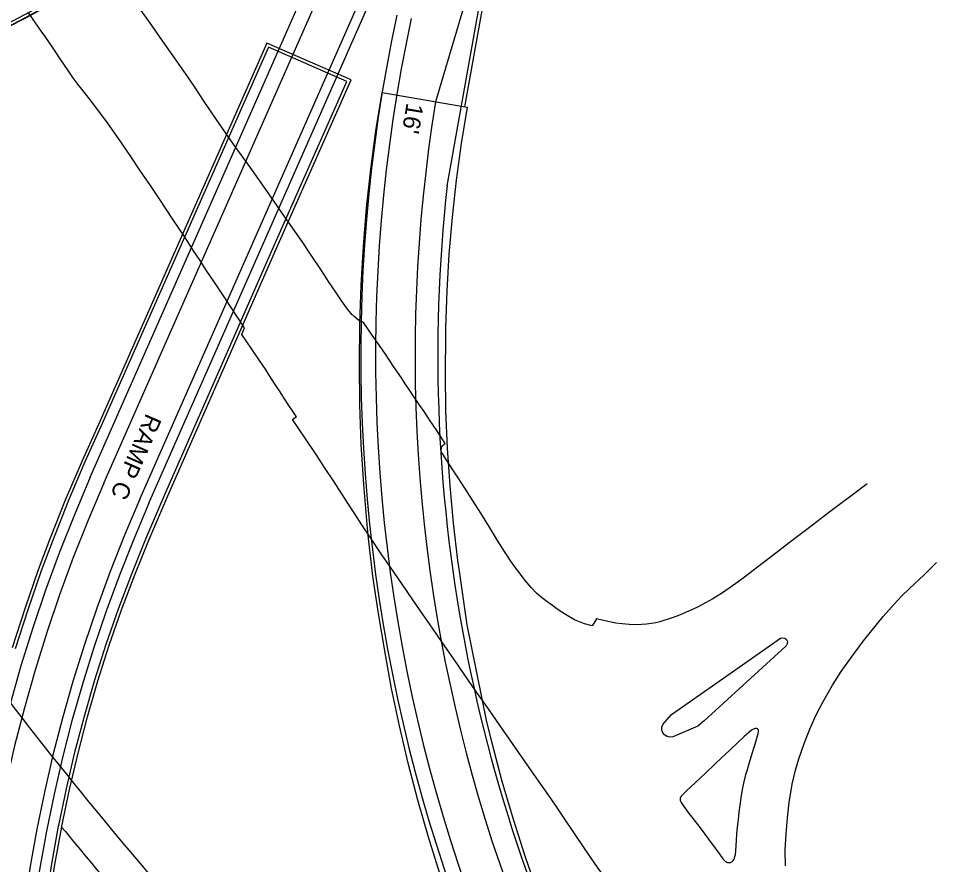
# Model space of a CAD drawing. Extents: x -5665 to 1997148, y 4 to 812485.
# Drawn here: x 1971429 to 1971801.5, y 795754.1 to 796097.4 of the extents above; entities that cross this region are included whole.
import ezdxf

# ---------------------------------------------------------------- set-up
doc = ezdxf.new("R2010")
doc.units = 0
for name, color, linetype in [('BR_CONCRETE', 7, 'Continuous'), ('RD_EX_Conc', 7, 'Continuous'), ('RD_EX_Road', 7, 'Continuous'), ('RD_PD_ALT1_TrvlWay', 7, 'Continuous'), ('RD_PD_FOC', 7, 'Continuous'), ('RD_PD_PaveShd', 7, 'Continuous'), ('RD_SHT_TX', 7, 'Continuous')]:
    doc.layers.add(name, color=color, linetype=linetype)

msp = doc.modelspace()

# ---------------------------------------------------------------- linework, layer by layer
at = {"layer": 'BR_CONCRETE'}
for points in [[(1971441.45, 795738.75), (1971443.85, 795754.1), (1971446.65, 795769.39), (1971446.7, 795769.67), (1971449.78, 795784.54), (1971453.24, 795799.32), (1971457.08, 795814.01), (1971461.3, 795828.59), (1971465.9, 795843.06), (1971470.88, 795857.4), (1971476.22, 795871.61), (1971481.93, 795885.68), (1971489.64, 795903.69), (1971508.7, 795947.03), (1971533.89, 796004.37), (1971564, 796072.42), (1971529.86, 796087.35), (1971462.02, 795933.76), (1971454.86, 795917.93), (1971448.05, 795901.93), (1971441.61, 795885.78), (1971437.04, 795873.62), (1971431.6, 795857.86), (1971426.53, 795841.97)], [(1971480.73, 795886.18), (1971488.45, 795904.21), (1971507.51, 795947.55), (1971532.7, 796004.9), (1971562.28, 796071.76), (1971530.53, 796085.64), (1971463.21, 795933.23), (1971456.05, 795917.41), (1971449.25, 795901.44), (1971442.82, 795885.31), (1971438.26, 795873.18), (1971432.83, 795857.45), (1971427.78, 795841.59)], [(1971577.67, 795840.74), (1971577.67, 795840.79), (1971575.07, 795855.91), (1971572.87, 795871.09), (1971571.06, 795886.32), (1971570.48, 795892.08), (1971569.12, 795908.28), (1971568.14, 795924.51), (1971567.57, 795940.76), (1971567.38, 795957.02), (1971567.6, 795973.28), (1971567.6, 795973.38), (1971568.11, 795989.11), (1971569.01, 796004.82), (1971570.3, 796020.5), (1971571.99, 796036.14), (1971574.07, 796051.74), (1971576.55, 796067.27), (1971611.09, 796061.35), (1971608.65, 796046.54), (1971606.6, 796031.66), (1971604.95, 796016.73), (1971603.68, 796001.77), (1971602.81, 795986.78), (1971602.34, 795971.77), (1971602.29, 795968.67), (1971602.12, 795953.43), (1971602.34, 795938.19), (1971602.96, 795922.97), (1971603.98, 795907.76), (1971605.39, 795892.58), (1971607.19, 795877.45), (1971607.78, 795873.09), (1971610.84, 795852.33), (1971611, 795851.32), (1971618.96, 795811.94), (1971621.04, 795803.46), (1971625.16, 795787.95), (1971629.67, 795772.54), (1971634.55, 795757.25), (1971639.81, 795742.09)], [(1971440.16, 795738.94), (1971442.57, 795754.32), (1971445.37, 795769.63), (1971445.43, 795769.92), (1971448.51, 795784.82), (1971451.98, 795799.63), (1971455.83, 795814.35), (1971460.06, 795828.97), (1971464.67, 795843.47), (1971469.66, 795857.84), (1971475.01, 795872.08), (1971480.73, 795886.18)], [(1971600.01, 795750.42), (1971595.33, 795765.23), (1971591.03, 795780.16), (1971587.11, 795795.18), (1971583.58, 795810.31), (1971580.43, 795825.51), (1971577.67, 795840.79), (1971577.67, 795840.74)]]:
    msp.add_lwpolyline(points, dxfattribs=at)
for radius, start in [(473.13, 234.9869), (472, 234.9869), (473.3, 235.2092)]:
    msp.add_arc((1971210.82, 796516.01), radius, start, 298.9233, dxfattribs=at)
at = {"layer": 'RD_EX_Conc'}
msp.add_lwpolyline([(1971740.3, 795842.64), (1971707.21, 795812.45), (1971704.68, 795810.22), (1971694.46, 795805.92), (1971693.3, 795805.79), (1971692.16, 795806.05), (1971691.18, 795806.67), (1971690.45, 795807.58), (1971690.06, 795808.68), (1971690.06, 795809.84), (1971690.45, 795810.94), (1971690.46, 795810.96), (1971694, 795814.93), (1971722.73, 795835.17), (1971738.2, 795845.95), (1971739.06, 795846.12), (1971739.91, 795845.9), (1971740.58, 795845.34), (1971740.94, 795844.54), (1971740.93, 795843.67), (1971740.53, 795842.88), (1971740.3, 795842.64)], dxfattribs=at)
msp.add_lwpolyline([(1971718.93, 795755.73), (1971719.18, 795756.12), (1971719.4, 795756.52), (1971719.5, 795756.74), (1971719.7, 795757.33), (1971719.88, 795758.18), (1971720.04, 795759.64), (1971720.17, 795761.71), (1971720.31, 795763.98), (1971720.48, 795766.4), (1971720.74, 795769.23), (1971721.1, 795772.43), (1971721.46, 795775.4), (1971721.81, 795778.14), (1971722.25, 795781.19), (1971722.78, 795784.48), (1971723.26, 795787.06), (1971723.68, 795788.91), (1971724.17, 795790.69), (1971724.75, 795792.61), (1971725.52, 795795.14), (1971726.43, 795798.21), (1971727.23, 795800.86), (1971727.88, 795802.99), (1971728.4, 795804.79), (1971728.82, 795806.25), (1971729.1, 795807.25), (1971729.25, 795807.81), (1971729.29, 795808.04), (1971729.3, 795808.25), (1971729.29, 795808.44), (1971729.26, 795808.61), (1971729.21, 795808.76), (1971729.14, 795808.9), (1971729.04, 795809.02), (1971728.93, 795809.12), (1971728.79, 795809.19), (1971728.63, 795809.23), (1971728.46, 795809.24), (1971728.08, 795809.22), (1971727.67, 795809.18), (1971727.44, 795809.12), (1971727.17, 795809.01), (1971726.46, 795808.62), (1971725.3, 795807.72), (1971723.41, 795806.02), (1971720.86, 795803.63), (1971717.72, 795800.67), (1971714.04, 795797.19), (1971711.73, 795794.99), (1971707.71, 795791.2), (1971703.64, 795787.36), (1971700.08, 795784.01), (1971698.05, 795781.93), (1971697.67, 795781.42), (1971697.53, 795781.09), (1971697.45, 795780.77), (1971697.42, 795780.46), (1971697.45, 795780.17), (1971697.59, 795779.8), (1971697.89, 795779.25), (1971699.01, 795777.62), (1971700.78, 795775.25), (1971703.16, 795772.1), (1971705.95, 795768.41), (1971708.94, 795764.4), (1971711.64, 795760.75), (1971713.52, 795758.13), (1971714.8, 795756.43), (1971715.29, 795755.87), (1971715.68, 795755.52), (1971716.03, 795755.29), (1971716.36, 795755.11), (1971716.68, 795754.97), (1971716.99, 795754.89), (1971717.29, 795754.85), (1971717.58, 795754.86), (1971717.86, 795754.93), (1971718.13, 795755.05), (1971718.38, 795755.2), (1971718.59, 795755.36), (1971718.77, 795755.54)], close=True, dxfattribs=at)
at = {"layer": 'RD_EX_Road'}
for points in [[(1971773.33, 795908.48), (1971767.3, 795903.98), (1971761.92, 795899.96), (1971757.15, 795896.37), (1971752.91, 795893.18), (1971748.82, 795890.07), (1971744.51, 795886.74), (1971739.95, 795883.21), (1971735.11, 795879.48), (1971730.63, 795876.03), (1971727.13, 795873.35), (1971724.1, 795871.05), (1971721.01, 795868.77), (1971717.74, 795866.46), (1971714.18, 795864.1), (1971710.71, 795861.93), (1971707.72, 795860.21), (1971705.04, 795858.79), (1971702.49, 795857.56), (1971699.94, 795856.42), (1971697.22, 795855.29), (1971694.67, 795854.3), (1971692.59, 795853.59), (1971690.83, 795853.06), (1971689.19, 795852.57), (1971687.54, 795852.15), (1971685.7, 795851.83), (1971683.77, 795851.6), (1971681.81, 795851.44), (1971679.57, 795851.4), (1971676.82, 795851.5), (1971673.95, 795851.73), (1971671.36, 795852.03), (1971668.18, 795852.63), (1971663.54, 795853.73), (1971661.78, 795850.99), (1971658.72, 795851.77), (1971654.62, 795853.39), (1971650.93, 795855.54), (1971648.03, 795857.45), (1971645.62, 795859.17), (1971643.38, 795860.8), (1971641.27, 795862.45), (1971639.23, 795864.25), (1971637.08, 795866.46), (1971634.65, 795869.37), (1971632.31, 795872.37), (1971630.41, 795874.85), (1971628.51, 795877.51), (1971626.18, 795881.07), (1971623.38, 795885.53), (1971620.08, 795890.91), (1971616.58, 795896.58), (1971613.19, 795901.91), (1971610.06, 795906.74), (1971607.36, 795910.91), (1971604.96, 795914.6), (1971602.78, 795918.03), (1971601.19, 795920.56), (1971600.56, 795921.56), (1971600.51, 795921.74), (1971600.51, 795922.05), (1971600.66, 795923.03), (1971600.84, 795923.61), (1971601.16, 795924.11), (1971601.62, 795924.53), (1971602.2, 795924.87), (1971598.72, 795930.13), (1971595.85, 795934.46), (1971593.58, 795937.86), (1971591.91, 795940.33), (1971590.52, 795942.39), (1971589.06, 795944.54), (1971587.55, 795946.79), (1971585.97, 795949.13), (1971584.38, 795951.5), (1971582.8, 795953.85), (1971581.24, 795956.18), (1971579.71, 795958.47), (1971577.89, 795961.16), (1971575.52, 795964.64), (1971572.58, 795968.91), (1971569.07, 795973.98), (1971567.92, 795974.47), (1971566.99, 795974.97), (1971566.19, 795975.56), (1971565.41, 795976.3), (1971564.74, 795976.95), (1971564.48, 795977.16), (1971564.27, 795977.29), (1971563.96, 795977.59), (1971562.56, 795979.42), (1971560.27, 795982.66), (1971558.02, 795985.94), (1971556.06, 795988.88), (1971554.85, 795990.67), (1971554.13, 795991.74), (1971551.7, 795995.44), (1971547.59, 796001.72), (1971544.11, 796006.91), (1971541.2, 796011.08), (1971536.1, 796018.39), (1971532.55, 796023.47), (1971529.13, 796028.39), (1971524.97, 796034.33), (1971523.72, 796036.05), (1971521.29, 796039.42), (1971517.26, 796045.04), (1971513.23, 796050.77), (1971509.28, 796056.52), (1971504.17, 796064.05), (1971501.1, 796068.58), (1971497.98, 796073.2), (1971492.37, 796081.35), (1971487.5, 796088.27), (1971482.56, 796095.22), (1971477.46, 796102.39)], [(1971666.22, 795749.76), (1971662.88, 795754.58), (1971658.27, 795761.26), (1971654.56, 795766.72), (1971649.88, 795773.7), (1971647.17, 795777.74), (1971644.2, 795782.09), (1971640.98, 795786.76), (1971637.5, 795791.75), (1971634.11, 795796.61), (1971628.54, 795804.58), (1971624.48, 795810.39), (1971621.19, 795815.09), (1971618.32, 795819.16), (1971614.64, 795824.42), (1971610.08, 795830.98), (1971605.47, 795837.62), (1971601.02, 795844.08), (1971596.96, 795849.97), (1971593.21, 795855.4), (1971589, 795861.5), (1971584.38, 795868.24), (1971580.25, 795874.26), (1971576.5, 795879.75), (1971571.48, 795887.27), (1971568.4, 795891.96), (1971565.2, 795896.84), (1971562.16, 795901.5), (1971559.27, 795905.95), (1971556.54, 795910.17), (1971553.52, 795914.79), (1971549.79, 795920.41), (1971545.34, 795927.03), (1971540.17, 795934.65), (1971541.81, 795935.81), (1971541.2, 795936.71), (1971540.19, 795938.21), (1971538.8, 795940.33), (1971537.03, 795943.04), (1971535.16, 795945.91), (1971533.49, 795948.46), (1971532.03, 795950.7), (1971530.77, 795952.63), (1971529.21, 795954.99), (1971526.86, 795958.53), (1971523.7, 795963.23), (1971519.73, 795969.11), (1971520.8, 795971.76), (1971517.61, 795976.6), (1971513.01, 795983.53), (1971508.42, 795990.45), (1971505.26, 795995.27), (1971502.74, 795999.11), (1971500.11, 796003.12), (1971496.64, 796008.42), (1971491.57, 796016.09), (1971486.4, 796023.88), (1971482.59, 796029.53), (1971479.83, 796033.6), (1971477.8, 796036.63), (1971475.16, 796040.56), (1971470.58, 796047.3), (1971465.17, 796055.01), (1971460.05, 796061.83), (1971455.86, 796067.24), (1971453.2, 796070.68), (1971451.19, 796073.4), (1971448.95, 796076.6), (1971446.3, 796080.49), (1971443.08, 796085.22), (1971439.86, 796089.94), (1971438.48, 796091.97), (1971436.01, 796095.53), (1971433.26, 796099.48)], [(1971740.15, 795753.55), (1971740.09, 795759.95), (1971740.42, 795766.52), (1971740.97, 795773.03), (1971741.74, 795779.27), (1971742.95, 795786.76), (1971744.28, 795792.37), (1971745.64, 795797.03), (1971747.75, 795803.17), (1971750.1, 795809.08), (1971752.42, 795814.33), (1971755.3, 795819.92), (1971759.24, 795826.8), (1971762.73, 795832.35), (1971766.94, 795838.28), (1971771.79, 795844.84), (1971776.94, 795851.14), (1971779.87, 795854.67), (1971784.26, 795859.72), (1971787.28, 795863.02), (1971790.54, 795866.13), (1971796.26, 795871.48), (1971801.5, 795876.62)]]:
    msp.add_lwpolyline(points, dxfattribs=at)
at = {"layer": 'RD_PD_ALT1_TrvlWay'}
for p, q in [((1971625.47, 796155.89), (1971598.28, 796063.55)), ((1971463.7, 795908.76), (1971561.57, 796130.77)), ((1971478.34, 795902.3), (1971576.21, 796124.32))]:
    msp.add_line(p, q, dxfattribs=at)
for centre, radius, start, end in [((1971210.82, 796516.01), 462, 234.9869, 298.9233), ((1972226.58, 795960.7), 652.66, 167.91315, 225.41147), ((1972226.58, 795960.7), 636.66, 170.70317, 225.41147), ((1972046.23, 795651.96), 636.62, 156.21044, 245.71509), ((1972046.23, 795651.96), 620.62, 156.21044, 245.71509), ((1972855.69, 796921.19), 1820, 219.26396, 221.68841)]:
    msp.add_arc(centre, radius, start, end, dxfattribs=at)
at = {"layer": 'RD_PD_FOC'}
msp.add_line((1971610.16, 796061.51), (1971626.93, 796155.58), dxfattribs=at)
at = {"layer": 'RD_PD_PaveShd'}
for p, q in [((1971482, 795900.69), (1971595.06, 796157.15)), ((1971602.93, 796029.49), (1971625.46, 796155.84)), ((1971458.21, 795911.18), (1971556.08, 796133.19))]:
    msp.add_line(p, q, dxfattribs=at)
for centre, radius, start, end in [((1971210.82, 796516.01), 472, 234.9869, 298.9233), ((1971210.82, 796516.01), 472, 234.9869, 298.9233), ((1972226.58, 795960.7), 658.66, 167.91315, 225.41147), ((1972226.58, 795960.7), 627.43, 173.70525, 208.85724), ((1972855.69, 796921.19), 1805, 211.88652, 221.68841), ((1972046.23, 795651.96), 642.62, 156.21044, 245.71509), ((1972046.23, 795651.96), 616.62, 156.21044, 245.71509)]:
    msp.add_arc(centre, radius, start, end, dxfattribs=at)

# ---------------------------------------------------------------- texts
at = {"layer": 'RD_SHT_TX'}
for s, rotation, p in [("16'", 260.4217, (1971586.56, 796063.3)), ('RAMP C', 246.2119, (1971480.93, 795937.45))]:
    msp.add_text(s, height=7, rotation=rotation, dxfattribs=at).set_placement(p)

doc.saveas('drawing.dxf')
